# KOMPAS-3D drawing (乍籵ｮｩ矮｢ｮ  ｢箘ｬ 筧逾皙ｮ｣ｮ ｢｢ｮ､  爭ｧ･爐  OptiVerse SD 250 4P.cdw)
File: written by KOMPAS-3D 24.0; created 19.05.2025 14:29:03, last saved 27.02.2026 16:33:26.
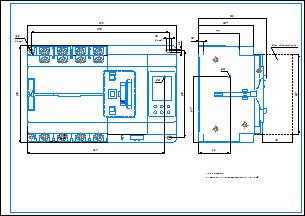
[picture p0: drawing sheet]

Document properties: Утвердил: Строгонов; Автор: keaz-admin; Проверил: Дорошев; Форматы листов документа: A2; Полное имя файла: D:\Проекты\OptiVerse SD\OptiVerse SD\OptiVerse SD 250 4P\КД\ГЖИК.648456.002 ГЧ OptiVerse SD 250 4P (без рамки).cdw; Масса: 8.9; Т. контр.: Пашков А.Е.; Наименование: Устройство автоматического ввода резерва OptiVerse SD 250 4P / Габаритный чертеж; Н. контр.: Гаврикова; Количество листов документа: 1; Разработал: Сулейманова

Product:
- Body: Тело 3
    Масса: 0.000026
- Body: Тело 4
    Масса: 0.000008
- Component [assembly]: RDS5-250.STEP  | qty 1  | pos. 1  | Масса: 34.785173; source file: ..\3D\RDS5-250.STEP.a3d

Views: Проекционный вид 2, Вид 1
Referenced files in D:\Проекты\OptiVerse SD\OptiVerse SD\OptiVerse SD 250 4P\КД\: ГЖИК.648456.002 СБ OptiVerse SD 250 4P.cdw
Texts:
  Зона обслуживания
  Устройство автоматического
  ввода резерва OptiVerse SD 250 4P
  Габаритный чертеж
  ГЖИК.648456.002ГЧ
  Сулейманова
  Дорошев
  ГЖИК.648456.002
  АО "КЭАЗ"
  Гаврикова
  Строгонов
  Пашков А.Е.
  Без основной надписи.
Dimensions and other numbers on the sheet: 132; 107; 10; 79; 90; 157; 129; 61; 1:1; 0; 1; 4; 8,9

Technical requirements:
  Ц.М. - центр масс.
  Отклонение координат от центра масс не более 10 %.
